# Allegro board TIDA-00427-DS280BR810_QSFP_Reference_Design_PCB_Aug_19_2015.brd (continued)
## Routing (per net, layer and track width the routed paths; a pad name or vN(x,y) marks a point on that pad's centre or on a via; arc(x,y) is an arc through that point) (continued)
RXN0_CABLE_TOP: length 68.6
  TOP w0.16: U1.A9 v2(94.73,68.6)
  ART09 w0.109: v2(94.73,68.6) 94.4,68.27 arc(94.37,68.22) 94.36,68.17 94.36,68.04 arc(94.4,67.95) 94.49,67.91 95.5,67.91 arc(95.85,67.98) 96.14,68.17 96.24,68.28 arc(96.97,68.76) 97.83,68.94 98.07,68.94 arc(99.84,69.67) 100.58,71.45 100.58,75.06 arc(100.9,76.68) 101.82,78.06 102.42,78.66 arc(105.33,80.6) 108.75,81.28 119.49,81.28 arc(120.26,81.13) 120.9,80.7 arc(121.66,80.19) 122.56,80.01 146.81,80.01 arc(148.34,79.38) 148.97,77.85 148.97,77.55 arc(149.03,77.26) 149.22,77.04 arc(149.4,76.89) 149.53,76.71 149.69,76.42 149.76,76.31 arc(149.84,76.24) 149.94,76.26 U9.U18
RXN0_HOST_BOT: length 73.7
  TOP w0.16: U2.B1 v2(113.59,63.27)
  ART11 w0.109: U8.L18 50.03,63.64 50.21,63.59 50.27,63.47 50.4,63.25 50.57,62.95 50.75,62.65 arc(51.1,61.79) 51.23,60.88 arc(51.31,60.45) 51.56,60.09 53.54,58.11 arc(54.61,57.4) 55.87,57.14 76.89,57.14 arc(78.11,56.9) 79.15,56.21 79.54,55.82 arc(80.79,54.98) 82.27,54.69 96.4,54.69 arc(101.86,55.77) 106.49,58.86 109.47,61.85 110.56,62.93 arc(111.75,63.73) 113.16,64.01 113.78,64.01 arc(113.9,63.96) 113.96,63.83 113.96,63.7 arc(113.95,63.65) 113.92,63.6 v2(113.59,63.27)
RXN0_HOST_TOP: length 69.6
  TOP w0.16: U2.A9 v2(112.53,71)
  ART09 w0.109: U8.U18 58.02,63.63 58.2,63.58 58.42,63.19 arc(58.46,63.13) 58.49,63.07 58.5,63.07 58.59,62.97 arc(58.77,62.68) 58.82,62.34 58.81,62.04 58.81,62.03 arc(59.68,59.92) 61.79,59.05 73.23,59.05 arc(74.4,58.82) 75.38,58.16 arc(77.01,57.07) 78.94,56.69 98.97,56.69 arc(102.47,57.39) 105.44,59.37 arc(105.46,59.38) 105.47,59.39 arc(105.48,59.4) 105.49,59.4 arc(105.49,59.41) 105.5,59.41 arc(105.5,59.41) 105.5,59.41 arc(105.5,59.41) 105.5,59.42 105.77,59.68 arc(107.29,61.96) 107.82,64.64 107.82,67.31 arc(107.96,68.01) 108.36,68.61 110.15,70.4 111.21,71.46 arc(111.46,71.63) 111.76,71.69 112.77,71.69 arc(112.86,71.65) 112.9,71.56 112.9,71.42 arc(112.89,71.37) 112.86,71.33 v2(112.53,71)
RXN1_CABLE_BOT: length 71.4
  TOP w0.132: 94.49,72.18 94.47,72.2 U1.A5
  TOP w0.16: 94.49,72.18 94.58,72.18 arc(94.71,72.16) 94.82,72.08 95,71.91 arc(95.17,71.77) 95.38,71.67 arc(95.52,71.64) 95.67,71.63 95.93,71.63 arc(96.24,71.68) 96.51,71.83 97.13,72.44 arc(97.29,72.55) v2(97.48,72.59)
  ART11 w0.109: U9.L21 153.94,76.26 arc(153.84,76.24) 153.76,76.31 153.69,76.42 153.53,76.71 arc(153.4,76.89) 153.22,77.04 arc(153.03,77.26) 152.97,77.55 152.97,77.77 arc(152.73,78.96) 152.06,79.97 150.24,81.79 arc(148.97,82.63) 147.48,82.93 129.51,82.93 arc(128.01,83.23) 126.75,84.07 arc(125.19,85.11) 123.36,85.48 118.87,85.48 arc(113.73,84.45) 109.37,81.54 100.46,72.63 arc(100.05,72.28) 99.58,72 arc(98.83,71.73) 98.04,71.63 97.51,71.63 arc(97.23,71.75) 97.11,72.03 97.11,72.16 arc(97.12,72.21) 97.15,72.25 v2(97.48,72.59)
RXN1_CABLE_TOP: length 62.5
  TOP w0.16: U1.A13 v2(94.73,65.4)
  ART11 w0.109: U9.U21 145.94,76.26 arc(145.84,76.24) 145.76,76.31 145.69,76.42 145.51,76.73 arc(145.23,77.07) 144.86,77.3 arc(144.54,77.39) 144.21,77.4 132.57,77.4 arc(127.49,78.41) 123.19,81.28 arc(122.2,81.94) 121.03,82.17 118.03,82.17 arc(114.71,81.51) 111.89,79.63 107.31,75.06 101.09,68.83 97.46,65.2 arc(96.56,64.6) 95.5,64.39 94.81,64.39 arc(94.49,64.52) 94.36,64.84 94.36,64.97 arc(94.37,65.02) 94.4,65.07 v2(94.73,65.4)
RXN1_HOST_BOT: length 67.5
  TOP w0.132: 112.84,67.4 U2.A5
  TOP w0.16: 112.84,67.4 112.8,67.4 112.78,67.42 112.69,67.42 arc(112.55,67.44) 112.44,67.52 112.27,67.69 arc(112.09,67.83) 111.88,67.92 arc(111.74,67.96) 111.59,67.97 111.34,67.97 arc(111.03,67.92) 110.75,67.77 110.14,67.16 arc(109.98,67.05) v2(109.78,67.01)
  ART11 w0.109: v2(109.78,67.01) 110.11,67.34 arc(110.14,67.39) 110.15,67.44 110.15,67.57 arc(110.04,67.83) 109.78,67.94 109.57,67.94 arc(108.39,67.76) 107.31,67.23 arc(107.05,67.03) 106.81,66.8 100.14,60.13 arc(97.68,58.49) 94.78,57.91 84.33,57.91 arc(83.37,58.1) 82.55,58.65 82.22,58.98 arc(81.02,59.78) 79.6,60.07 58.29,60.07 arc(56.5,60.55) 55.19,61.87 54.64,62.83 54.27,63.47 54.21,63.59 54.03,63.64 U8.L21
RXN1_HOST_TOP: length 65.1
  TOP w0.16: U2.A13 v2(112.53,74.2)
  ART09 w0.109: U8.U21 62.02,63.63 62.2,63.58 62.42,63.19 arc(62.44,63.16) 62.45,63.13 62.46,63.13 62.52,63.01 arc(62.76,62.73) 63.1,62.59 63.1,62.58 arc(63.65,62.51) 64.22,62.48 74.37,62.48 arc(75.87,62.18) 77.13,61.34 arc(78.9,60.16) 80.98,59.74 98.1,59.74 arc(100.77,60.27) 103.03,61.78 arc(103.05,61.79) 103.06,61.8 arc(103.07,61.81) 103.08,61.82 arc(103.08,61.82) 103.08,61.82 arc(103.09,61.82) 103.09,61.83 arc(103.09,61.83) 103.09,61.83 103.24,61.98 arc(104.56,63.96) 105.03,66.29 105.03,70.96 arc(105.34,72.53) 106.23,73.86 arc(106.79,74.34) 107.43,74.72 arc(108.4,75.07) 109.43,75.18 112.48,75.18 arc(112.78,75.06) 112.9,74.76 112.9,74.62 arc(112.89,74.57) 112.86,74.53 v2(112.53,74.2)
RXN2_CABLE_BOT: length 74.9
  TOP w0.16: U1.A3 v2(94.73,74.2)
  ART09 w0.109: U9.L15 157.94,73.86 arc(157.84,73.84) 157.76,73.91 157.69,74.02 157.43,74.48 arc(157.03,74.87) 156.48,74.99 arc(156.01,75.19) 155.82,75.66 155.82,76.55 arc(155.61,77.56) 155.04,78.42 153.26,80.2 arc(151.78,81.19) 150.03,81.53 124.31,81.53 arc(122.95,81.8) 121.79,82.58 arc(121.34,82.88) 120.81,82.98 108.92,82.98 arc(104.68,82.14) 101.09,79.74 100.53,79.18 arc(99.93,78.47) 99.46,77.67 arc(99.06,76.52) 98.93,75.31 arc(98.52,74.33) 97.54,73.92 96.16,73.92 arc(95.96,73.88) 95.78,73.76 arc(95.5,73.58) 95.18,73.51 94.49,73.51 arc(94.4,73.55) 94.36,73.64 94.36,73.77 arc(94.37,73.82) 94.4,73.87 v2(94.73,74.2)
RXN2_CABLE_TOP: length 70.8
  TOP w0.132: U1.A11 94.38,67.4 94.39,67.41
  TOP w0.16: 94.39,67.41 94.4,67.42 94.61,67.42 arc(94.69,67.43) 94.75,67.47 94.87,67.59 95,67.72 arc(95.18,67.86) 95.38,67.94 arc(95.49,67.96) 95.6,67.97 95.93,67.97 arc(96.26,67.91) 96.54,67.75 97.14,67.15 arc(97.29,67.05) v2(97.48,67.01)
  ART09 w0.109: U9.U15 149.94,73.86 arc(149.84,73.84) 149.76,73.91 149.69,74.02 149.43,74.48 arc(149.03,74.87) 148.48,74.99 arc(148.01,75.19) 147.82,75.66 147.82,76.66 arc(147.71,77.19) 147.41,77.64 arc(146.75,78.08) 145.97,78.23 121.48,78.23 arc(120.62,78.4) 119.89,78.89 arc(119.13,79.4) 118.23,79.58 108.5,79.58 arc(106.08,79.1) 104.03,77.73 103.22,76.92 arc(102.3,75.54) 101.98,73.91 101.98,70.34 arc(101.58,68.36) 100.46,66.67 arc(100.1,66.37) 99.69,66.12 arc(99.02,65.87) 98.31,65.79 97.78,65.79 arc(97.31,65.98) 97.11,66.45 97.11,66.59 arc(97.12,66.64) 97.15,66.68 v2(97.48,67.01)
RXN2_HOST_BOT: length 73.1
  TOP w0.16: U2.A3 v2(112.53,65.4)
  ART11 w0.109: U8.L15 50.03,66.04 50.21,65.99 50.27,65.87 50.57,65.35 arc(50.91,65.02) 51.37,64.92 arc(51.86,64.72) 52.05,64.24 52.05,63.76 arc(52.3,62.54) 52.99,61.5 54.17,60.32 arc(56,59.1) 58.16,58.67 77.78,58.67 arc(79.63,58.3) 81.2,57.25 81.51,56.95 arc(82.27,56.44) 83.16,56.26 96.52,56.26 arc(100.98,57.15) 104.76,59.67 110.49,65.41 arc(111.33,65.97) 112.33,66.17 112.69,66.17 arc(112.84,66.11) 112.9,65.96 112.9,65.82 arc(112.89,65.77) 112.86,65.73 v2(112.53,65.4)
RXN2_HOST_TOP: length 71.6
  TOP w0.16: U2.A11 112.89,72.2 112.87,72.18 112.65,72.18 arc(112.57,72.17) 112.51,72.12 112.39,72.01 112.26,71.87 arc(112.09,71.74) 111.89,71.66 arc(111.78,71.64) 111.67,71.63 111.34,71.63 arc(111.01,71.69) 110.72,71.85 110.13,72.44 arc(109.97,72.55) v2(109.78,72.59)
  ART09 w0.109: U8.U15 57.96,66 arc(58.08,66.05) 58.2,65.98 58.41,65.67 58.67,65.29 arc(58.97,65.03) 59.36,64.94 arc(59.88,64.73) 60.09,64.21 60.09,63.44 arc(60.23,62.74) 60.62,62.15 60.97,61.8 arc(62.33,60.89) 63.93,60.57 74.17,60.57 arc(75.27,60.36) 76.19,59.74 arc(77.83,58.65) 79.75,58.26 98.56,58.26 arc(101.68,58.88) 104.32,60.65 104.55,60.88 arc(105.94,62.95) 106.43,65.41 106.43,69.4 arc(106.65,70.85) 107.31,72.17 arc(107.56,72.48) 107.82,72.77 107.92,72.87 arc(108.52,73.27) 109.22,73.41 109.89,73.41 arc(110.08,73.33) 110.15,73.14 110.15,73.01 arc(110.14,72.96) 110.11,72.92 v2(109.78,72.59)
RXN3_CABLE_BOT: length 72
  TOP w0.16: U1.A7 v2(94.73,71)
  ART11 w0.109: v2(94.73,71) 94.4,70.67 arc(94.37,70.62) 94.36,70.57 94.36,70.44 arc(94.46,70.2) 94.7,70.1 98.42,70.1 arc(99.07,70.16) 99.69,70.31 arc(100.54,70.7) 101.27,71.28 110.81,80.83 arc(114.42,83.23) 118.66,84.08 122.09,84.08 arc(123.92,83.71) 125.48,82.68 arc(126.74,81.83) 128.24,81.53 147.15,81.53 arc(148.48,81.27) 149.61,80.52 150.49,79.63 arc(151.49,78.13) 151.85,76.37 151.85,75.93 arc(152.05,75.3) 152.63,74.98 arc(153.12,74.79) 153.48,74.4 153.69,74.02 153.76,73.91 arc(153.84,73.84) 153.94,73.86 U9.L24
RXN3_CABLE_TOP: length 65.1
  TOP w0.16: v2(93.68,63.27) 93.64,63.27 arc(93.52,63.31) 93.44,63.41 93.35,63.63 arc(93.34,63.67) 93.33,63.72 U1.B15
  ART11 w0.109: v2(93.68,63.27) 93.35,62.94 arc(93.32,62.9) 93.31,62.85 93.31,62.71 arc(93.41,62.46) 93.67,62.36 94.11,62.36 arc(96.69,62.87) 98.88,64.33 107.31,72.77 112.47,77.93 arc(112.56,78.02) 112.65,78.11 arc(115.18,79.7) 118.11,80.26 119.67,80.26 arc(121.16,79.97) 122.43,79.12 arc(122.97,78.6) 123.52,78.11 arc(124.29,77.47) 125.09,76.88 arc(130.67,74.11) 136.83,73.16 141.48,73.16 arc(142.13,73.29) 142.69,73.66 143.75,74.72 arc(144.09,74.95) 144.49,75.03 arc(144.87,74.95) 145.18,74.74 145.38,74.55 arc(145.41,74.51) 145.43,74.48 145.52,74.32 145.69,74.02 145.76,73.91 arc(145.84,73.84) 145.94,73.86 U9.U24
RXN3_HOST_BOT: length 68.1
  TOP w0.16: U2.A7 v2(112.53,68.6)
  ART11 w0.109: U8.L24 54.02,66.03 54.2,65.98 54.27,65.87 54.46,65.53 arc(54.75,65.17) 55.14,64.93 arc(55.36,64.88) 55.58,64.89 arc(55.92,64.73) 56.05,64.39 56.05,63.68 arc(56.24,62.76) 56.76,61.97 56.77,61.97 arc(57.23,61.69) 57.77,61.59 81.61,61.59 arc(82.81,61.35) 83.83,60.67 84.3,60.2 arc(84.89,59.8) 85.59,59.66 95.5,59.66 arc(96.65,59.89) 97.63,60.54 103.76,66.67 arc(105.41,68.01) 107.31,68.96 arc(109.03,69.44) 110.81,69.6 112.46,69.6 arc(112.77,69.47) 112.9,69.16 112.9,69.02 arc(112.89,68.97) 112.86,68.93 v2(112.53,68.6)
RXN3_HOST_TOP: length 67.3
  TOP w0.16: v2(113.59,76.33) 113.62,76.33 arc(113.74,76.29) 113.82,76.19 113.91,75.97 arc(113.93,75.92) 113.93,75.88 U2.B15
  ART09 w0.109: U8.U24 62.02,66.03 62.2,65.98 62.42,65.59 arc(62.83,65.13) 63.38,64.86 arc(63.7,64.72) 63.93,64.46 arc(64.44,63.94) 65.15,63.75 75.85,63.75 arc(77.25,63.47) 78.43,62.68 arc(80.06,61.6) 81.97,61.21 97.92,61.21 arc(99.91,61.61) 101.6,62.74 102.12,63.26 arc(103.24,64.93) 103.63,66.91 103.63,71.22 arc(104.13,73.71) 105.54,75.82 arc(106.37,76.49) 107.31,76.98 arc(108.25,77.25) 109.22,77.34 113.5,77.34 arc(113.82,77.21) 113.96,76.88 113.96,76.75 arc(113.95,76.7) 113.92,76.66 v2(113.59,76.33)
RXP0_CABLE_BOT: length 74.9
  TOP w0.16: U1.C1 v2(92.68,76.33)
  ART09 w0.109: U9.L17 157.48,76 arc(157.55,76.08) 157.53,76.18 157.47,76.29 157.29,76.6 arc(157.25,76.66) 157.2,76.7 arc(157.15,76.74) 157.1,76.79 arc(156.89,77.13) 156.81,77.52 156.81,77.72 arc(156.6,78.81) 155.98,79.73 154.69,81.03 arc(152.72,82.34) 150.41,82.8 125.14,82.8 arc(123.94,83.04) 122.93,83.71 arc(122.26,84.16) 121.46,84.32 108.84,84.32 arc(103.79,83.32) 99.5,80.45 98.77,79.72 arc(98.26,78.97) 98.05,78.09 arc(98.05,78.04) 98.05,77.98 arc(97.94,77.41) 97.61,76.93 96.7,76.02 arc(95.92,75.49) 94.99,75.31 93.51,75.31 arc(93.18,75.44) 93.05,75.77 93.05,75.9 arc(93.04,75.95) 93.01,75.99 v2(92.68,76.33)
RXP0_CABLE_TOP: length 68.6
  TOP w0.16: v2(93.73,68.6) 93.73,68.64 arc(93.72,68.68) 93.7,68.71 93.47,68.94 arc(93.41,68.98) U1.B9
  ART09 w0.109: v2(93.73,68.6) 94.06,68.27 arc(94.09,68.22) 94.1,68.17 94.1,68.04 arc(94.22,67.77) 94.49,67.65 95.5,67.65 arc(95.93,67.74) 96.3,67.98 arc(96.31,67.99) 96.33,68 arc(96.34,68.01) 96.34,68.01 arc(96.35,68.02) 96.35,68.02 arc(96.35,68.02) 96.36,68.02 arc(96.36,68.03) 96.36,68.03 96.42,68.09 arc(97.07,68.52) 97.83,68.68 98.07,68.68 arc(100.03,69.49) 100.84,71.45 100.84,75.06 arc(101.14,76.58) 102.01,77.88 102.6,78.47 arc(105.42,80.36) 108.75,81.02 119.49,81.02 arc(120.16,80.89) 120.72,80.51 arc(121.56,79.95) 122.56,79.75 146.81,79.75 arc(148.16,79.19) 148.71,77.85 148.71,77.55 arc(148.8,77.14) 149.08,76.82 arc(149.2,76.71) 149.3,76.58 149.47,76.29 149.53,76.18 arc(149.55,76.08) 149.48,76 U9.U17
RXP0_HOST_BOT: length 73.6
  TOP w0.16: U2.C1 v2(114.59,63.27)
  ART11 w0.109: v2(114.59,63.27) 114.25,63.6 arc(114.22,63.65) 114.21,63.7 114.21,63.83 arc(114.09,64.14) 113.78,64.27 113.16,64.27 arc(111.65,63.97) 110.37,63.11 106.31,59.05 arc(101.76,56.01) 96.4,54.95 82.27,54.95 arc(80.89,55.22) 79.72,56 79.37,56.36 arc(79.36,56.36) 79.36,56.36 arc(79.36,56.36) 79.36,56.36 arc(79.36,56.37) 79.35,56.37 arc(79.34,56.38) 79.34,56.38 arc(79.32,56.39) 79.31,56.4 arc(78.2,57.14) 76.89,57.4 55.87,57.4 arc(54.71,57.64) 53.72,58.29 51.74,60.27 arc(51.55,60.55) 51.49,60.88 arc(51.35,61.86) 50.97,62.77 50.8,63.08 50.43,63.71 50.48,63.89 U8.L17
RXP0_HOST_TOP: length 69.5
  TOP w0.16: v2(113.53,71) 113.53,70.96 arc(113.54,70.92) 113.56,70.89 113.79,70.66 arc(113.86,70.61) U2.B9
  ART09 w0.109: U8.U17 58.89,64.13 58.47,63.89 58.42,63.71 58.45,63.67 58.54,63.5 58.65,63.32 arc(58.67,63.28) 58.69,63.25 58.69,63.25 58.78,63.15 arc(59.01,62.77) 59.08,62.33 59.07,62.03 arc(59.86,60.11) 61.79,59.31 73.23,59.31 arc(74.5,59.06) 75.56,58.34 arc(77.11,57.31) 78.94,56.95 98.97,56.95 arc(102.39,57.63) 105.28,59.56 105.58,59.86 arc(107.05,62.06) 107.56,64.64 107.56,67.31 arc(107.72,68.11) 108.18,68.79 110,70.61 111.03,71.65 arc(111.36,71.87) 111.76,71.95 112.77,71.95 arc(113.05,71.83) 113.16,71.56 113.16,71.42 arc(113.17,71.37) 113.2,71.33 v2(113.53,71)
RXP1_CABLE_BOT: length 71.5
  TOP w0.132: 94.47,72.58 94.46,72.57 94.13,72.57 arc(93.99,72.54) 93.87,72.46 93.7,72.3 arc(93.6,72.22) 93.47,72.2 U1.B5
  TOP w0.16: 94.47,72.58 94.48,72.59 94.58,72.59 arc(94.87,72.53) 95.11,72.37 95.28,72.2 arc(95.39,72.11) 95.5,72.06 arc(95.59,72.04) 95.67,72.03 95.93,72.03 arc(96.32,72.2) v2(96.48,72.59)
  ART11 w0.109: v2(96.48,72.59) 96.81,72.25 arc(96.84,72.21) 96.85,72.16 96.85,72.03 arc(97.04,71.57) 97.51,71.37 98.04,71.37 arc(98.89,71.47) 99.69,71.77 arc(100.2,72.07) 100.65,72.45 109.55,81.36 arc(113.83,84.21) 118.87,85.22 123.36,85.22 arc(125.09,84.87) 126.56,83.89 arc(127.91,82.99) 129.51,82.67 147.48,82.67 arc(148.88,82.39) 150.06,81.6 151.84,79.82 arc(151.84,79.82) 151.84,79.82 arc(151.84,79.82) 151.85,79.82 151.88,79.79 arc(152.49,78.86) 152.71,77.77 152.71,77.55 arc(152.8,77.14) 153.08,76.82 arc(153.2,76.71) 153.3,76.58 153.47,76.29 153.53,76.18 arc(153.55,76.08) 153.48,76 U9.L22
RXP1_CABLE_TOP: length 62.5
  TOP w0.16: U1.B13 93.33,65.8 v2(93.73,65.4)
  ART11 w0.109: U9.U22 145.48,76 arc(145.55,76.08) 145.53,76.18 145.47,76.29 145.29,76.61 arc(145.06,76.88) 144.76,77.06 arc(144.51,77.13) 144.25,77.14 arc(144.24,77.14) 144.23,77.14 arc(144.23,77.14) 144.22,77.14 arc(144.22,77.14) 144.22,77.14 132.57,77.14 arc(127.39,78.17) 123.01,81.1 arc(122.1,81.7) 121.03,81.92 118.03,81.92 arc(114.81,81.27) 112.07,79.45 107.5,74.87 101.28,68.65 97.64,65.01 arc(96.66,64.36) 95.5,64.13 94.81,64.13 arc(94.31,64.34) 94.1,64.84 94.1,64.97 arc(94.09,65.02) 94.06,65.07 v2(93.73,65.4)
RXP1_HOST_BOT: length 67.6
  TOP w0.132: 112.84,67.03 113.13,67.03 arc(113.27,67.06) 113.39,67.14 113.56,67.3 arc(113.67,67.37) 113.79,67.4 U2.B5
  TOP w0.16: 112.84,67.03 112.8,67.03 112.78,67.01 112.68,67.01 arc(112.4,67.07) 112.15,67.23 111.98,67.4 arc(111.88,67.48) 111.76,67.54 arc(111.68,67.56) 111.59,67.56 111.34,67.56 arc(110.94,67.4) v2(110.78,67.01)
  ART11 w0.109: 54.86,62.96 55.01,62.7 55.41,62 arc(56.63,60.77) 58.29,60.33 79.6,60.33 arc(81.1,60.02) 82.38,59.17 arc(82.4,59.16) 82.41,59.15 arc(82.42,59.15) 82.43,59.14 arc(82.43,59.14) 82.43,59.13 arc(82.44,59.13) 82.44,59.13 arc(82.44,59.13) 82.44,59.13 82.73,58.83 arc(83.47,58.34) 84.33,58.17 94.78,58.17 arc(97.58,58.73) 99.95,60.31 106.62,66.99 arc(106.88,67.23) 107.17,67.44 arc(108.31,68.01) 109.57,68.2 109.78,68.2 arc(110.23,68.02) 110.41,67.57 110.41,67.44 arc(110.42,67.39) 110.45,67.34 v2(110.78,67.01)
  ART11 w0.132: U8.L22 54.48,63.89 54.43,63.71 54.5,63.6 54.86,62.96 54.73,63.19
RXP1_HOST_TOP: length 64.9
  TOP w0.16: U2.B13 v2(113.53,74.2)
  ART09 w0.109: v2(113.53,74.2) 113.2,74.53 arc(113.17,74.57) 113.16,74.62 113.16,74.76 arc(112.96,75.24) 112.48,75.44 109.43,75.44 arc(108.34,75.32) 107.31,74.95 arc(106.64,74.55) 106.05,74.04 arc(105.1,72.63) 104.77,70.96 104.77,66.29 arc(104.33,64.06) 103.06,62.17 102.87,61.98 arc(100.68,60.51) 98.1,60 80.98,60 arc(79,60.39) 77.32,61.52 arc(75.97,62.42) 74.37,62.74 64.22,62.74 arc(63.68,62.76) 63.14,62.84 arc(62.91,62.94) 62.75,63.14 62.68,63.25 62.68,63.25 arc(62.66,63.28) 62.65,63.32 62.54,63.5 62.43,63.69 62.42,63.71 62.47,63.89 62.89,64.13 U8.U22
RXP2_CABLE_BOT: length 74.9
  TOP w0.16: U1.B3 v2(93.73,74.2)
  ART09 w0.109: U9.L14 157.48,73.6 arc(157.55,73.68) 157.53,73.78 157.47,73.89 157.2,74.36 arc(156.9,74.65) 156.5,74.73 156.48,74.73 arc(155.83,75.01) 155.56,75.66 155.56,76.55 arc(155.37,77.46) 154.86,78.23 153.08,80.01 arc(151.68,80.95) 150.03,81.27 124.31,81.27 arc(122.85,81.57) 121.61,82.39 arc(121.24,82.64) 120.81,82.72 108.92,82.72 arc(104.78,81.9) 101.27,79.55 100.71,79 arc(100.14,78.32) 99.69,77.56 arc(99.32,76.46) 99.19,75.31 arc(98.7,74.14) 97.54,73.66 96.16,73.66 arc(96.06,73.64) 95.97,73.58 arc(95.6,73.34) 95.18,73.25 94.49,73.25 arc(94.22,73.37) 94.1,73.64 94.1,73.77 arc(94.09,73.82) 94.06,73.87 v2(93.73,74.2)
RXP2_CABLE_TOP: length 70.8
  TOP w0.132: 94.38,67.03 94.13,67.03 arc(93.99,67.06) 93.87,67.14 93.7,67.3 arc(93.6,67.37) 93.47,67.4 U1.B11
  TOP w0.16: 94.38,67.03 94.38,67.03 94.4,67.01 94.62,67.01 arc(94.85,67.06) 95.04,67.19 95.29,67.44 arc(95.38,67.51) 95.48,67.55 arc(95.54,67.56) 95.6,67.56 95.93,67.56 arc(96.32,67.4) v2(96.48,67.01)
  ART09 w0.109: v2(96.48,67.01) 96.81,66.68 arc(96.84,66.64) 96.85,66.59 96.85,66.45 arc(97.12,65.8) 97.78,65.53 98.31,65.53 arc(99.08,65.62) 99.81,65.89 arc(100.25,66.16) 100.64,66.49 arc(101.82,68.26) 102.23,70.34 102.23,73.91 arc(102.54,75.44) 103.4,76.73 104.22,77.55 arc(106.18,78.86) 108.5,79.32 118.23,79.32 arc(119.03,79.16) 119.7,78.71 arc(120.52,78.16) 121.48,77.97 145.97,77.97 arc(146.65,77.84) 147.23,77.45 arc(147.47,77.09) 147.56,76.66 147.56,75.66 arc(147.83,75.01) 148.48,74.73 148.5,74.73 arc(148.9,74.65) 149.2,74.36 149.47,73.89 149.53,73.78 arc(149.55,73.68) 149.48,73.6 U9.U14
RXP2_HOST_BOT: length 72.9
  TOP w0.16: U2.B3 v2(113.53,65.4)
  ART11 w0.109: v2(113.53,65.4) 113.2,65.73 arc(113.17,65.77) 113.16,65.82 113.16,65.96 arc(113.02,66.29) 112.69,66.43 112.33,66.43 arc(111.25,66.21) 110.33,65.6 arc(110.31,65.59) 110.3,65.58 arc(110.29,65.57) 110.28,65.57 arc(110.28,65.56) 110.28,65.56 arc(110.27,65.56) 110.27,65.55 arc(110.27,65.55) 110.27,65.55 104.58,59.86 arc(100.88,57.39) 96.52,56.52 83.16,56.52 arc(82.37,56.68) 81.69,57.13 81.42,57.4 arc(81.42,57.4) 81.42,57.4 arc(81.42,57.4) 81.42,57.4 arc(81.41,57.41) 81.41,57.41 arc(81.4,57.42) 81.39,57.42 arc(81.38,57.44) 81.36,57.45 arc(79.72,58.54) 77.78,58.93 58.16,58.93 arc(56.1,59.34) 54.36,60.5 53.17,61.69 arc(52.54,62.64) 52.31,63.76 52.31,64.24 arc(52.04,64.9) 51.37,65.18 51.36,65.18 arc(51.03,65.25) 50.79,65.48 50.5,66 50.43,66.11 50.48,66.3 U8.L14
RXP2_HOST_TOP: length 71.5
  TOP w0.132: 112.95,72.57 113.13,72.57 arc(113.27,72.54) 113.39,72.46 113.56,72.3 arc(113.67,72.22) 113.79,72.2 U2.B11
  TOP w0.16: 112.95,72.57 112.89,72.57 112.87,72.59 112.65,72.59 arc(112.42,72.54) 112.22,72.41 111.97,72.16 arc(111.88,72.09) 111.78,72.05 arc(111.72,72.04) 111.67,72.03 111.34,72.03 arc(110.94,72.2) v2(110.78,72.59)
  ART09 w0.109: U8.U14 58.41,66.26 arc(58.4,66.19) 58.42,66.12 58.63,65.81 58.88,65.44 arc(59.09,65.26) 59.36,65.2 arc(60.06,64.91) 60.35,64.21 60.35,63.44 arc(60.47,62.84) 60.81,62.33 61.16,61.98 arc(62.43,61.13) 63.93,60.83 74.17,60.83 arc(75.36,60.6) 76.38,59.92 arc(77.93,58.88) 79.75,58.52 98.56,58.52 arc(101.58,59.12) 104.14,60.83 104.37,61.06 arc(105.7,63.05) 106.17,65.41 106.17,69.4 arc(106.41,70.93) 107.1,72.32 arc(107.36,72.65) 107.64,72.95 107.74,73.05 arc(108.42,73.51) 109.22,73.67 109.89,73.67 arc(110.26,73.51) 110.41,73.14 110.41,73.01 arc(110.42,72.96) 110.45,72.92 v2(110.78,72.59)
RXP3_CABLE_BOT: length 72
  TOP w0.16: U1.B7 v2(93.73,71)
  ART11 w0.109: v2(93.73,71) 94.06,70.67 arc(94.09,70.62) 94.1,70.57 94.1,70.44 arc(94.28,70.02) 94.7,69.84 98.42,69.84 arc(99.11,69.9) 99.78,70.06 arc(100.67,70.48) 101.45,71.1 111,80.64 arc(114.51,82.99) 118.66,83.82 122.09,83.82 arc(123.82,83.48) 125.29,82.49 arc(126.64,81.59) 128.24,81.27 147.15,81.27 arc(148.38,81.03) 149.42,80.33 150.31,79.45 arc(151.26,78.03) 151.59,76.37 151.59,75.93 arc(151.85,75.13) 152.59,74.72 arc(152.97,74.57) 153.25,74.27 153.47,73.89 153.53,73.78 arc(153.55,73.68) 153.48,73.6 U9.L25
RXP3_CABLE_TOP: length 65
  TOP w0.16: U1.C15 v2(92.68,63.27)
  ART11 w0.109: U9.U25 145.48,73.6 arc(145.55,73.68) 145.53,73.78 145.47,73.89 145.26,74.25 145.23,74.31 145.21,74.34 arc(145.2,74.35) 145.19,74.36 145,74.56 arc(144.77,74.71) 144.49,74.77 arc(144.19,74.71) 143.93,74.54 142.87,73.48 arc(142.23,73.05) 141.48,72.9 136.83,72.9 arc(130.59,73.86) 124.95,76.66 arc(124.13,77.27) 123.35,77.91 arc(122.79,78.41) 122.24,78.94 arc(121.06,79.73) 119.67,80 118.11,80 arc(115.27,79.46) 112.83,77.92 arc(112.74,77.83) 112.66,77.75 107.5,72.59 99.06,64.15 arc(96.79,62.63) 94.11,62.1 93.67,62.1 arc(93.23,62.28) 93.05,62.71 93.05,62.85 arc(93.04,62.9) 93.01,62.94 v2(92.68,63.27)
RXP3_HOST_BOT: length 68
  TOP w0.16: U2.B7 v2(113.53,68.6)
  ART11 w0.109: v2(113.53,68.6) 113.2,68.93 arc(113.17,68.97) 113.16,69.02 113.16,69.16 arc(112.96,69.65) 112.46,69.86 110.81,69.86 arc(108.99,69.69) 107.22,69.21 arc(105.27,68.23) 103.58,66.86 97.45,60.73 arc(96.55,60.13) 95.5,59.92 85.59,59.92 arc(84.99,60.04) 84.49,60.38 84.05,60.82 arc(84.05,60.82) 84.05,60.82 arc(84.05,60.82) 84.04,60.82 84.01,60.85 arc(82.91,61.59) 81.61,61.85 57.77,61.85 arc(57.33,61.93) 56.94,62.16 56.94,62.16 arc(56.48,62.86) 56.31,63.68 56.31,64.39 arc(56.09,64.93) 55.55,65.15 arc(55.39,65.13) 55.24,65.17 arc(54.92,65.37) 54.68,65.66 54.49,66 54.42,66.11 54.47,66.29 54.89,66.53 U8.L25
RXP3_HOST_TOP: length 67.1
  TOP w0.16: U2.C15 v2(114.59,76.33)
  ART09 w0.109: U8.U25 62.89,66.53 62.47,66.29 62.42,66.11 62.45,66.07 62.54,65.9 62.65,65.72 arc(62.98,65.33) 63.44,65.12 arc(63.85,64.92) 64.15,64.58 arc(64.57,64.16) 65.15,64.01 75.85,64.01 arc(77.35,63.71) 78.61,62.87 arc(80.15,61.83) 81.97,61.47 97.92,61.47 arc(99.81,61.85) 101.42,62.92 101.94,63.44 arc(103,65.03) 103.37,66.91 103.37,71.22 arc(103.89,73.81) 105.35,76 arc(106.22,76.71) 107.22,77.22 arc(108.2,77.51) 109.22,77.6 113.5,77.6 arc(114,77.39) 114.21,76.88 114.21,76.75 arc(114.22,76.7) 114.25,76.66 v2(114.59,76.33)
SCL: length 286.2
  TOP w0.183: U2.F12 v2(117.53,72.6) ; U1.F12 v2(89.73,67)
  ART02 w0.132: v2(117.53,72.6) 116.85,73.28 102.57,73.28 98.98,69.7 92.43,69.7 v2(89.73,67)
  ART04 w0.132: J18.6 15.49,35.94 15.49,44.58 16.76,45.85 18.49,45.85 J23.4 22.91,44.53 26.67,40.77 48.71,40.77 53.66,45.72 J3.1 81.89,67.92 88.81,67.92 v2(89.73,67) 89.86,67 90.42,67.56 90.42,68.2 89,69.62 84.68,69.62 82.3,72.01 82.3,85.47 81.41,86.36 81.41,88.98 J22.4 ; v2(117.53,72.6) 117.53,70.56 118.24,69.85 121.92,69.85 125.02,66.75 125.02,34.42 116.84,26.25 J4.3 116.84,25.53 118.11,24.26 126.24,24.26 144.27,42.29 173.74,42.29 175.9,44.45
SDA: length 271
  TOP w0.183: U1.E12 v2(91.33,67) ; U2.E12 v2(115.93,72.6)
  ART02 w0.132: v2(91.33,67) 92.01,66.32 102.18,66.32 105.82,69.95 114.48,69.95 115.93,71.41 v2(115.93,72.6)
  ART04 w0.132: v2(115.93,72.6) 116.38,73.05 119.61,73.05 125.48,67.18 125.48,34.16 119.38,28.07 J4.4 120.62,24.8 125.7,24.8 143.83,42.93 171.83,42.93 J24.3 ; J22.3 82.68,72.17 84.84,70 89.26,70 91.33,67.93 v2(91.33,67) 90.88,66.55 90.04,66.55 89.81,66.32 82.83,66.32 J3.2 61.15,44.64 53.28,44.64 48.9,40.26 26.29,40.26 23.24,43.31 19.18,43.31 17.96,44.53 J23.3 16.13,43.38 16.13,37.85 J18.5
TOP_INTL_CABLE: length 33.2
  TOP w0.183: J14.4 145.34,48.77 149.1,48.77 v1(150.5,50.16) 150.62,50.29 R45.1
  ART04 w0.132: v1(150.5,50.16) 149.86,50.8 149.86,60.33 147.58,62.62 147.58,69.46 146.12,70.93 U9.U28
TOP_INTL_HOST: length 61.3
  TOP w0.183: J13.4 28.63,48.26 31.11,48.26 v1(32.38,49.53) R41.1
  ART04 w0.132: v1(32.38,49.53) 33.78,48.13 33.78,44.16 35.69,42.26 47.91,42.26 54.56,48.9 54.56,53.35 60.37,59.16 60.37,66.84 60.95,67.42 61.53,67.42 62.89,68.78 U8.U28
TOP_LPMODE_CABLE: length 24.3
  ART04 w0.132: J14.8 149.22,47.57 149.22,57.39 143.89,62.73 143.89,67.41 U9.U31
TOP_LPMODE_HOST: length 58.3
  ART04 w0.132: U8.U31 64.22,69.99 64.22,62.4 54.99,53.17 54.99,48.6 48.11,41.72 33.4,41.72 31.24,43.88 31.24,45.8 J13.8
TOP_MODPRSL_CABLE: length 40.6
  TOP w0.183: R46.1 153.16,50.29 v1(153.03,50.16) 151.26,48.39 J14.10 150.16,45.97 142.19,45.97 J14.2
  ART04 w0.132: U9.U27 147.91,70.22 147.91,63.16 152.4,58.67 152.4,50.8 v1(153.03,50.16)
TOP_MODPRSL_HOST: length 64.3
  TOP w0.183: R42.1 v1(34.92,49.53) 35.05,49.4 J13.10 33.83,45.85 26.11,45.85 J13.2
  ART04 w0.132: U8.U27 61.02,68.13 60.03,67.13 60.03,59.5 54.08,53.55 54.08,49.1 47.71,42.73 37.59,42.73 36.45,43.88 36.45,48.01 v1(34.92,49.53)
TOP_MODSELL_CABLE: length 32.3
  ART04 w0.132: U9.U8 150.29,68.53 151.51,67.31 151.51,60.96 153.67,58.8 153.67,49.66 152.53,48.51 152.53,46.48 151.89,45.85 147.4,45.85 146.18,47.07
TOP_MODSELL_HOST: length 66.8
  ART04 w0.132: J13.6 28.83,45.92 28.83,43.75 31.37,41.21 48.32,41.21 55.5,48.39 55.5,52.96 64.6,62.06 64.6,70.4 63.12,71.88 62.69,71.88 62.13,71.33 U8.U8
TXN0_CABLE_BOT: length 44.9
  TOP w0.16: U2.H1 v2(119.08,63.27)
  ART09 w0.109: v2(119.08,63.27) 118.75,63.27 118.59,63.12 118.59,62.71 arc(118.78,62.27) 119.22,62.08 126.32,62.08 arc(128.12,61.72) 129.64,60.71 131.35,59 arc(132.88,57.97) 134.7,57.61 149.43,57.61 arc(152.86,59.03) 154.28,62.47 154.28,62.69 arc(154.25,62.9) 154.16,63.1 153.58,64.11 153.16,64.11 153.01,63.96 U9.L37
TXN0_CABLE_TOP: length 34.5
  TOP w0.16: U2.J9 v2(120.13,71)
  ART09 w0.109: v2(120.13,71) 119.76,71 119.61,70.85 119.61,70.51 arc(119.79,70.08) 120.21,69.91 124.46,69.91 arc(124.78,69.9) 125.09,69.88 arc(128.01,69.13) 130.48,67.41 134.8,63.09 arc(136.32,62.08) 138.11,61.72 145.48,61.72 arc(146.09,61.98) 146.35,62.59 146.35,62.74 arc(146.33,62.85) 146.28,62.95 145.58,64.03 145.16,64.03 145.01,63.88 U9.U37
TXN0_HOST_BOT: length 42.5
  TOP w0.16: U1.H1 v2(88.19,76.33)
  ART09 w0.109: v2(88.19,76.33) 88.54,76.33 88.7,76.48 88.7,76.71 arc(88.65,76.92) 88.54,77.1 88.33,77.3 87.15,78.49 arc(84.84,80.03) 82.12,80.57 57.07,80.57 arc(54.65,79.56) 53.64,77.14 53.64,76.99 arc(53.69,76.77) 53.81,76.58 54.06,76.21 54.15,76.07 54.36,75.77 54.66,75.77 54.89,75.99 U8.L37
TXN0_HOST_TOP: length 30.4
  TOP w0.16: U1.J9 v2(87.13,68.6)
  ART09 w0.109: U8.U37 62.74,76.13 62.46,75.84 62.46,75.6 62.71,75.23 62.95,74.98 arc(63.18,74.83) 63.45,74.78 63.7,74.78 arc(64.2,74.68) 64.61,74.4 64.8,74.22 arc(65.27,73.9) 65.83,73.79 77.75,73.79 arc(79.51,73.44) 80.99,72.45 84.86,68.58 arc(85.6,68.08) 86.48,67.91 87.29,67.91 arc(87.51,68) 87.6,68.22 87.6,68.45 87.45,68.6 v2(87.13,68.6)
TXN1_CABLE_BOT: length 49.3
  TOP w0.132: 119.87,67.4 U2.J5
  TOP w0.16: 119.87,67.4 119.88,67.42 119.98,67.42 arc(120.11,67.44) 120.22,67.52 120.4,67.69 arc(120.57,67.83) 120.78,67.92 arc(120.92,67.96) 121.07,67.97 121.41,67.97 arc(121.72,67.91) 121.99,67.75 122.62,67.12 arc(122.74,67.04) v2(122.88,67.01)
  ART11 w0.109: v2(122.88,67.01) 122.76,67.13 122.56,67.13 122.33,66.9 122.33,66.4 arc(122.38,66.15) 122.52,65.94 122.7,65.75 130.14,58.31 arc(132.22,56.93) 134.66,56.44 148.29,56.44 arc(150.96,56.97) 153.23,58.49 156.88,62.13 arc(157.18,62.34) 157.54,62.41 157.66,62.41 arc(157.87,62.45) 158.05,62.57 158.12,62.64 158.17,62.69 arc(158.21,62.76) 158.23,62.84 arc(158.2,63.04) 158.12,63.22 arc(158.06,63.31) 158.01,63.39 157.61,64.01 157.29,64.01 U9.L2
TXN1_CABLE_TOP: length 41.8
  TOP w0.16: U2.J13 v2(120.13,74.2)
  ART11 w0.109: U9.U2 149.01,63.85 149.12,63.96 149.68,63.96 150.14,63.14 arc(150.21,63.01) 150.24,62.87 arc(150.24,62.84) 150.24,62.81 150.24,62.64 arc(149.5,60.85) 147.72,60.11 138.48,60.11 arc(135.8,60.65) 133.53,62.17 133.43,62.26 126.76,68.93 126.1,69.59 124.75,70.95 arc(123.7,71.64) 122.47,71.89 120.8,71.89 arc(119.96,72.24) 119.61,73.08 119.61,74.05 119.76,74.2 v2(120.13,74.2)
TXN1_HOST_BOT: length 48.6
  TOP w0.132: 87.38,72.18 87.4,72.2 U1.J5
  TOP w0.16: 87.38,72.18 87.29,72.18 arc(87.15,72.16) 87.04,72.08 86.87,71.91 arc(86.69,71.77) 86.48,71.67 arc(86.34,71.64) 86.19,71.63 85.85,71.63 arc(85.54,71.68) 85.27,71.85 84.64,72.48 arc(84.52,72.56) v2(84.38,72.59)
  ART11 w0.109: v2(84.38,72.59) 84.79,72.59 84.94,72.74 84.94,73.18 arc(84.85,73.62) 84.6,74 84.25,74.35 78.27,80.33 arc(74.91,82.57) 70.94,83.36 60.59,83.36 arc(56.68,82.59) 53.37,80.37 50.83,77.83 arc(50.52,77.58) 50.14,77.5 arc(50.01,77.47) 49.91,77.39 49.77,77.25 arc(49.71,77.15) 49.68,77.04 49.68,76.91 arc(49.7,76.78) 49.76,76.67 50.3,75.82 50.75,75.82 50.89,75.96 U8.L2
TXN1_HOST_TOP: length 40.6
  TOP w0.16: U1.J13 v2(87.13,65.4)
  ART11 w0.109: v2(87.13,65.4) 87.18,65.35 87.53,65.35 87.68,65.51 87.68,66.03 arc(87.2,67.2) 86.03,67.69 85.65,67.69 arc(83.88,68.04) 82.39,69.04 75.7,75.72 arc(75.7,75.73) 75.7,75.73 arc(75.7,75.73) 75.69,75.73 75.66,75.76 arc(71.43,78.59) 66.45,79.58 60.02,79.58 arc(58.35,78.89) 57.66,77.22 57.66,77.04 arc(57.68,76.89) 57.73,76.76 58.22,75.92 58.68,75.92 U8.U2
TXN2_CABLE_BOT: length 45.2
  TOP w0.16: U2.J3 v2(120.13,65.4)
  ART09 w0.109: v2(120.13,65.4) 119.76,65.77 119.76,65.9 arc(119.8,66) 119.9,66.04 124.36,66.04 arc(124.72,66.03) 125.07,66.01 arc(127.89,65.26) 130.28,63.59 133.65,60.22 arc(134.88,59.39) 136.33,59.11 147.09,59.11 arc(150.45,60.5) 151.84,63.86 151.84,67.03 arc(151.94,67.33) 152.2,67.51 152.65,67.51 arc(152.88,67.46) 153.06,67.32 153.43,66.73 153.43,66.73 153.59,66.47 153.59,66.27 153.42,66.09 153.05,66.09 U9.L34
TXN2_CABLE_TOP: length 31.3
  TOP w0.132: U2.J11 119.73,72.2
  TOP w0.16: 119.73,72.2 119.78,72.2 119.8,72.18 119.82,72.18 arc(120.25,72.36) 120.42,72.78 arc(120.53,73.05) 120.8,73.16 121.93,73.16 arc(122.11,73.12) 122.27,73.02 arc(122.32,72.74) 122.08,72.59 v2(121.88,72.59)
  ART09 w0.109: U9.U34 145.17,65.96 145.39,65.96 145.54,66.11 145.54,66.62 145.08,67.32 144.99,67.42 arc(144.84,67.52) 144.65,67.56 138.37,67.56 arc(136.15,68) 134.28,69.25 133.78,69.75 arc(131.99,70.95) 129.87,71.37 123.27,71.37 arc(122.69,71.61) 122.45,72.19 122.45,72.45 122.31,72.59 v2(121.88,72.59)
TXN2_HOST_BOT: length 42.3
  TOP w0.16: U1.J3 v2(87.13,74.2)
  ART09 w0.109: U8.L34 54.75,73.73 54.51,73.48 54.51,73.15 54.57,73.06 54.87,72.68 54.97,72.58 arc(55.18,72.44) 55.42,72.39 55.6,72.39 arc(55.92,72.52) 56.05,72.85 56.05,76 arc(56.18,76.64) 56.54,77.18 arc(57.97,78.13) 59.65,78.47 77.94,78.47 arc(79.54,78.15) 80.9,77.24 83.13,75.01 83.36,74.78 arc(84.74,73.86) 86.36,73.54 87.41,73.54 arc(87.6,73.62) 87.68,73.81 87.68,74.05 87.53,74.2 v2(87.13,74.2)
TXN2_HOST_TOP: length 30.8
  TOP w0.132: 87.45,67.42 87.46,67.41 87.48,67.41 87.49,67.4 U1.J11
  TOP w0.16: 87.45,67.42 87.25,67.42 arc(87.17,67.43) 87.11,67.47 87,67.59 86.86,67.72 arc(86.69,67.86) 86.49,67.94 arc(86.38,67.96) 86.27,67.97 85.94,67.97 arc(85.61,67.91) 85.32,67.75 84.73,67.15 arc(84.57,67.05) v2(84.38,67.01)
  ART09 w0.109: U8.U34 62.61,73.73 62.46,73.58 62.46,73.3 62.8,72.69 arc(63.05,72.46) 63.37,72.39 64.12,72.39 arc(64.88,72.24) 65.53,71.81 arc(65.81,71.62) 66.13,71.56 73.63,71.56 arc(75.93,71.1) 77.88,69.8 80.67,67.01 arc(81.25,66.56) 81.92,66.29 arc(82.26,66.22) 82.62,66.2 84.56,66.2 arc(84.81,66.3) 84.91,66.55 84.91,66.9 84.76,67.06 84.43,67.06 v2(84.38,67.01)
TXN3_CABLE_BOT: length 51
  TOP w0.16: U2.J7 v2(120.13,68.6)
  ART11 w0.109: U9.L5 157.48,66.13 157.61,66.25 157.61,66.55 157.06,67.31 arc(156.87,67.48) 156.62,67.54 156.46,67.54 arc(156.05,67.38) 155.85,66.98 155.85,63.8 arc(155.72,63.14) 155.34,62.57 154.3,61.52 arc(150.41,58.93) 145.82,58.01 138.8,58.01 arc(135.08,58.75) 131.93,60.86 125.09,67.69 124.34,68.45 arc(122.98,69.35) 121.39,69.67 120.19,69.67 arc(119.89,69.55) 119.76,69.24 119.76,68.97 v2(120.13,68.6)
TXN3_CABLE_TOP: length 45.1
  TOP w0.16: U2.H15 v2(119.08,76.33)
  ART11 w0.109: v2(119.08,76.33) 118.82,76.33 118.67,76.48 118.67,76.89 arc(118.77,77.14) 119.02,77.24 119.53,77.24 arc(120.89,76.97) 122.05,76.2 134.21,64.03 arc(136.86,62.27) 139.98,61.65 145.88,61.65 arc(147.28,62.23) 147.86,63.63 147.86,67.11 arc(147.98,67.39) 148.26,67.51 148.72,67.51 arc(148.91,67.46) 149.06,67.33 149.56,66.55 149.56,66.24 149.44,66.13 U9.U5
TXN3_HOST_BOT: length 50.5
  TOP w0.16: U1.J7 v2(87.13,71)
  ART11 w0.109: U8.L5 50.61,73.73 50.44,73.56 50.44,73.27 50.97,72.52 arc(51.1,72.42) 51.26,72.39 51.57,72.39 arc(51.91,72.53) 52.05,72.87 52.05,76.24 arc(52.25,77.25) 52.83,78.11 53.14,78.42 arc(56.84,80.9) 61.21,81.77 69.19,81.77 arc(72.7,81.07) 75.68,79.08 83.1,71.67 83.97,70.8 arc(84.76,70.27) 85.7,70.08 87.1,70.08 arc(87.46,70.23) 87.6,70.59 87.6,70.85 87.45,71 v2(87.13,71)
TXN3_HOST_TOP: length 43.9
  TOP w0.16: U1.H15 v2(88.19,63.27)
  ART11 w0.109: U8.U5 58.59,73.73 58.37,73.51 58.37,73.33 59.02,72.46 arc(59.19,72.35) 59.39,72.31 59.63,72.31 arc(59.94,72.44) 60.07,72.75 60.07,75.95 arc(60.64,77.33) 62.03,77.91 64.11,77.91 arc(70.49,76.64) 75.89,73.03 78.56,70.36 86,62.92 arc(86.6,62.52) 87.3,62.38 88.29,62.38 arc(88.58,62.5) 88.7,62.79 88.7,63.12 88.54,63.27 v2(88.19,63.27)
TXP0_CABLE_BOT: length 45.1
  TOP w0.16: U2.G1 v2(118.08,63.27)
  ART09 w0.109: U9.L36 154,64.11 154,63.91 154.38,63.23 154.38,63.23 arc(154.5,62.97) 154.54,62.69 154.54,62.47 arc(153.04,58.85) 149.43,57.35 134.7,57.35 arc(132.79,57.73) 131.17,58.82 129.46,60.52 arc(128.02,61.49) 126.32,61.82 119.22,61.82 arc(118.59,62.08) 118.33,62.71 118.33,63.02 v2(118.08,63.27)
TXP0_CABLE_TOP: length 34.7
  TOP w0.16: U2.H9 v2(119.13,71)
  ART09 w0.109: U9.U36 145.96,64.08 145.96,63.92 146.49,63.1 146.49,63.09 arc(146.58,62.92) 146.61,62.74 146.61,62.59 arc(146.28,61.79) 145.48,61.46 138.11,61.46 arc(136.23,61.84) 134.64,62.9 arc(134.62,62.91) 134.61,62.92 arc(134.6,62.93) 134.59,62.93 arc(134.59,62.94) 134.58,62.94 arc(134.58,62.94) 134.58,62.94 arc(134.58,62.95) 134.58,62.95 130.3,67.23 arc(127.9,68.9) 125.08,69.62 arc(124.77,69.64) 124.46,69.65 120.21,69.65 arc(119.6,69.9) 119.35,70.51 119.35,70.78 v2(119.13,71)
TXP0_HOST_BOT: length 42.7
  TOP w0.16: U1.G1 v2(89.19,76.33)
  ART09 w0.109: v2(89.19,76.33) 88.96,76.56 88.96,76.71 arc(88.89,77.02) 88.72,77.28 88.42,77.58 87.33,78.67 arc(84.94,80.27) 82.12,80.83 57.07,80.83 arc(54.47,79.75) 53.39,77.14 53.39,76.94 arc(53.44,76.68) 53.58,76.46 53.85,76.07 53.85,75.69 U8.L36
TXP0_HOST_TOP: length 30.6
  TOP w0.16: U1.H9 v2(88.13,68.6)
  ART09 w0.109: v2(88.13,68.6) 87.86,68.33 87.86,68.22 arc(87.7,67.82) 87.29,67.65 86.48,67.65 arc(85.5,67.84) 84.68,68.4 80.81,72.27 arc(79.41,73.2) 77.75,73.53 65.83,73.53 arc(65.18,73.66) 64.64,74.03 arc(64.62,74.03) 64.6,74.05 arc(64.6,74.05) 64.59,74.06 arc(64.59,74.06) 64.58,74.07 arc(64.58,74.07) 64.58,74.07 arc(64.58,74.07) 64.58,74.07 64.43,74.22 arc(64.1,74.44) 63.7,74.52 63.45,74.52 arc(63.07,74.59) 62.75,74.81 62.52,75.04 62.49,75.09 62.27,75.41 61.57,75.41 U8.U36
TXP1_CABLE_BOT: length 49.5
  TOP w0.132: 119.88,67.01 119.86,67.03 119.53,67.03 arc(119.39,67.06) 119.27,67.14 119.1,67.3 arc(119,67.37) 118.87,67.4 U2.H5
  TOP w0.16: v2(121.88,67.01) 121.88,67.1 arc(121.74,67.43) 121.41,67.56 121.07,67.56 arc(120.99,67.56) 120.9,67.54 arc(120.79,67.48) 120.68,67.4 120.51,67.23 arc(120.27,67.07) 119.98,67.01 119.88,67.01
  ART11 w0.109: U9.L3 157.98,64.09 157.98,63.92 158.33,63.36 arc(158.45,63.11) 158.49,62.84 arc(158.45,62.66) 158.35,62.5 158.3,62.45 158.23,62.39 arc(157.97,62.21) 157.66,62.15 157.54,62.15 arc(157.28,62.1) 157.06,61.95 154.64,59.53 153.41,58.3 arc(151.06,56.73) 148.29,56.18 134.66,56.18 arc(132.12,56.69) 129.96,58.13 122.52,65.57 122.33,65.75 arc(122.14,66.05) 122.07,66.4 122.07,66.83 v2(121.88,67.01)
TXP1_CABLE_TOP: length 42
  TOP w0.16: U2.H13 v2(119.13,74.2)
  ART11 w0.109: U9.U3 150.01,64.12 150.01,63.91 150.42,63.19 arc(150.48,63.04) 150.5,62.89 150.5,62.64 arc(149.69,60.67) 147.72,59.86 138.48,59.86 arc(135.7,60.41) 133.34,61.98 126.58,68.75 125.09,70.23 124.56,70.76 arc(123.61,71.4) 122.47,71.63 120.8,71.63 arc(119.78,72.05) 119.35,73.08 119.35,73.98 v2(119.13,74.2)
TXP1_HOST_BOT: length 48.8
  TOP w0.132: U1.H5 88.39,72.2 arc(88.27,72.22) 88.16,72.3 87.99,72.46 arc(87.87,72.54) 87.73,72.57 87.4,72.57 87.39,72.57 87.37,72.59
  TOP w0.16: v2(85.38,72.59) 85.38,72.5 arc(85.52,72.17) 85.85,72.03 86.19,72.03 arc(86.28,72.04) 86.36,72.06 arc(86.48,72.11) 86.58,72.2 86.75,72.37 arc(87,72.53) 87.28,72.59 87.37,72.59
  ART11 w0.109: U8.L3 49.92,75.76 49.92,75.93 49.55,76.52 arc(49.45,76.71) 49.42,76.91 49.42,77.04 arc(49.47,77.25) 49.59,77.44 49.7,77.55 arc(49.9,77.7) 50.14,77.75 arc(50.36,77.8) 50.56,77.92 53.19,80.56 arc(56.59,82.82) 60.59,83.62 70.94,83.62 arc(75.01,82.81) 78.45,80.51 84.44,74.53 84.78,74.18 arc(85.09,73.72) 85.2,73.18 85.2,72.77 v2(85.38,72.59)
TXP1_HOST_TOP: length 40.8
  TOP w0.16: U1.H13 v2(88.13,65.4)
  ART11 w0.109: v2(88.13,65.4) 87.94,65.59 87.94,66.03 arc(87.38,67.39) 86.03,67.94 85.65,67.94 arc(83.98,68.28) 82.57,69.22 75.85,75.94 arc(71.53,78.83) 66.45,79.84 60.02,79.84 arc(58.17,79.07) 57.4,77.22 57.4,77.04 arc(57.43,76.83) 57.51,76.63 arc(57.55,76.56) 57.58,76.5 57.89,75.97 57.89,75.73 U8.U3
TXP2_CABLE_BOT: length 45.4
  TOP w0.16: U2.H3 v2(119.13,65.4)
  ART09 w0.109: U9.L33 154.26,66.78 153.75,66.78 153.63,66.89 153.36,67.33 arc(153.07,67.65) 152.65,67.77 152.16,67.77 arc(152.14,67.77) 152.12,67.76 arc(151.73,67.48) 151.58,67.03 151.58,63.86 arc(150.27,60.68) 147.09,59.36 136.33,59.36 arc(134.98,59.63) 133.83,60.4 130.46,63.77 arc(128,65.49) 125.09,66.27 arc(124.73,66.29) 124.36,66.3 119.9,66.3 arc(119.62,66.18) 119.5,65.9 119.5,65.77 v2(119.13,65.4)
TXP2_CABLE_TOP: length 31.5
  TOP w0.132: 119.64,72.57 119.53,72.57 arc(119.39,72.54) 119.27,72.46 119.1,72.3 arc(119,72.22) 118.87,72.2 U2.H11
  TOP w0.16: v2(122.88,72.59) 122.88,72.75 arc(122.84,72.96) 122.72,73.15 122.55,73.31 arc(122.27,73.5) 121.93,73.57 120.8,73.57 arc(120.25,73.34) 120.02,72.78 arc(119.96,72.64) 119.82,72.59 119.8,72.59 119.78,72.57 119.64,72.57
  ART09 w0.109: v2(122.88,72.59) 122.71,72.41 122.71,72.19 arc(122.87,71.79) 123.27,71.63 129.87,71.63 arc(132.09,71.19) 133.97,69.93 134.46,69.44 arc(136.25,68.24) 138.37,67.82 144.65,67.82 arc(144.93,67.76) 145.17,67.6 145.29,67.49 145.44,67.26 145.48,67.18 145.72,66.83 146.31,66.83 U9.U33
TXP2_HOST_BOT: length 42.4
  TOP w0.16: U1.H3 v2(88.13,74.2)
  ART09 w0.109: U8.L33 53.59,73.03 54.25,73.03 54.38,72.89 54.58,72.63 54.68,72.51 54.79,72.39 arc(55.08,72.2) 55.42,72.13 55.6,72.13 arc(56.1,72.34) 56.31,72.85 56.31,76 arc(56.42,76.54) 56.72,76.99 arc(58.07,77.89) 59.65,78.21 77.94,78.21 arc(79.44,77.91) 80.71,77.06 82.95,74.82 83.18,74.6 arc(84.64,73.62) 86.36,73.28 87.41,73.28 arc(87.78,73.44) 87.94,73.81 87.94,74.01 v2(88.13,74.2)
TXP2_HOST_TOP: length 31
  TOP w0.132: U1.H11 88.39,67.4 arc(88.27,67.37) 88.16,67.3 87.99,67.14 arc(87.87,67.06) 87.73,67.03 87.48,67.03 87.46,67.01
  TOP w0.16: 87.46,67.01 87.25,67.01 arc(87.02,67.06) 86.82,67.19 86.57,67.44 arc(86.48,67.51) 86.38,67.55 arc(86.32,67.56) 86.27,67.56 85.94,67.56 arc(85.54,67.4) v2(85.38,67.01)
  ART09 w0.109: v2(85.38,67.01) 85.17,66.8 85.17,66.55 arc(84.99,66.12) 84.56,65.94 82.62,65.94 arc(82.23,65.96) 81.85,66.04 arc(81.12,66.34) 80.49,66.82 77.69,69.62 arc(75.83,70.86) 73.63,71.3 66.13,71.3 arc(65.71,71.38) 65.35,71.62 arc(64.79,72) 64.12,72.13 63.38,72.13 arc(62.92,72.23) 62.58,72.56 62.29,73.08 62.23,73.17 62.22,73.19 62.04,73.24 U8.U33
TXP3_CABLE_BOT: length 51.1
  TOP w0.16: U2.H7 v2(119.13,68.6)
  ART11 w0.109: v2(119.13,68.6) 119.5,68.97 119.5,69.24 arc(119.7,69.73) 120.19,69.93 121.39,69.93 arc(123.08,69.59) 124.52,68.63 125.28,67.87 132.11,61.04 arc(135.18,58.99) 138.8,58.27 145.82,58.27 arc(150.31,59.17) 154.11,61.71 155.16,62.76 arc(155.48,63.24) 155.6,63.8 155.6,66.99 arc(155.87,67.56) 156.46,67.8 156.62,67.8 arc(156.97,67.72) 157.25,67.49 157.69,66.88 157.82,66.75 158.24,66.75 U9.L6
TXP3_CABLE_TOP: length 45.3
  TOP w0.16: U2.G15 v2(118.08,76.33)
  ART11 w0.109: v2(118.08,76.33) 118.41,76.66 118.41,76.89 arc(118.59,77.32) 119.02,77.5 119.53,77.5 arc(120.99,77.21) 122.23,76.38 134.4,64.22 arc(136.96,62.51) 139.98,61.9 145.88,61.9 arc(147.1,62.41) 147.6,63.63 147.6,67.11 arc(147.79,67.58) 148.26,67.77 148.72,67.77 arc(149.03,67.7) 149.27,67.49 149.65,66.89 149.76,66.78 150.26,66.78 U9.U6
TXP3_HOST_BOT: length 50.7
  TOP w0.16: U1.H7 v2(88.13,71)
  ART11 w0.109: v2(88.13,71) 87.86,70.73 87.86,70.59 arc(87.64,70.04) 87.1,69.82 85.7,69.82 arc(84.66,70.03) 83.78,70.61 82.91,71.48 75.5,78.89 arc(72.61,80.83) 69.19,81.51 61.21,81.51 arc(56.94,80.66) 53.32,78.24 53.01,77.93 arc(52.49,77.15) 52.31,76.24 52.31,72.87 arc(52.09,72.35) 51.57,72.13 51.26,72.13 arc(51,72.18) 50.78,72.34 arc(50.77,72.35) 50.76,72.35 50.7,72.44 arc(50.69,72.46) 50.68,72.48 50.33,72.98 50.24,73.08 49.64,73.08 U8.L6
TXP3_HOST_TOP: length 44.1
  TOP w0.16: U1.G15 v2(89.19,63.27)
  ART11 w0.109: v2(89.19,63.27) 88.96,63.04 88.96,62.79 arc(88.76,62.32) 88.29,62.12 87.3,62.12 arc(86.5,62.28) 85.82,62.74 78.37,70.18 75.71,72.84 arc(70.39,76.4) 64.11,77.65 62.03,77.65 arc(60.82,77.15) 60.33,75.95 60.33,72.75 arc(60.12,72.26) 59.63,72.05 59.39,72.05 arc(59.09,72.11) 58.84,72.27 arc(58.83,72.28) 58.83,72.29 58.31,72.97 58.18,73.1 57.66,73.1 U8.U6
VUSB: length 68
  ART04 w0.254: v1(92.71,29.21) 91.06,29.21 89.39,30.88 89.39,34.31 88.39,35.31 80.77,35.31 71.75,26.29 68.44,26.29 66.79,24.64 37.97,24.64 v1(37.47,24.13) v1(37.47,22.86)
  BOTTOM w0.254: U3.66 93.56,30.44 92.71,29.59 v1(92.71,29.21)
WP: length 5.6
  TOP w0.183: J18.7 13.97,31.11 J19.2
N16780616: length 19.1
  TOP w0.305: v1(97.79,34.29) 97.8,34.3 C32.2 99.81,34.3 100.46,33.66 101.09,33.66 101.85,34.42 103.2,34.42 104.22,35.43 Y1.1
  BOTTOM w0.254: 96.12,29.06 96,28.94 U3.69
  BOTTOM w0.305: 96.12,29.06 96.52,29.46 96.52,33.02 v1(97.79,34.29)
N16780624: length 17.4
  TOP w0.305: v1(97.79,32.38) 97.8,32.38 C31.2 99.81,32.38 100.46,33.02 101.22,33.02 101.98,33.78 103.63,33.78 104.22,33.2 Y1.2
  BOTTOM w0.254: U3.70 96.39,28.44 96.54,28.6
  BOTTOM w0.305: v1(97.79,32.38) 97.79,32.37 97.16,31.73 97.16,29.21 96.54,28.6
N16780665: length 10.5
  BOTTOM w0.203: U3.72 96.76,27.44 100.48,23.72 J2.1
N16780674: length 7.3
  TOP w0.183: Q1.1 82.05,16.65 v1(82.55,17.14)
  BOTTOM w0.203: v1(82.55,17.14) 82.55,17.78 85.28,20.51 U3.15
N16780676: length 20.9
  BOTTOM w0.203: J2.8 104.52,17.37 104.52,25.02 104.27,25.27 99.95,25.27 97.28,27.94 U3.71
N16780680: length 11.4
  BOTTOM w0.203: J2.3 102.13,21.18 96.37,26.94 U3.73
N16780690: length 12.7
  BOTTOM w0.203: J2.5 102.9,18.64 101.6,19.94 101.6,20.83 95.98,26.44 U3.74
N16780698: length 14.3
  BOTTOM w0.203: J2.7 100.33,19.02 100.33,21.08 95.47,25.94 U3.75
N16780708: length 20.2
  TOP w0.183: v1(95.89,24.13) 96.52,23.5 C30.1 98.4,22.85 R25.1 99.05,22.87 100.33,21.59 100.33,13.94 J2.11
  BOTTOM w0.183: U3.76 95.21,25.44 95.89,24.77 v1(95.89,24.13)
N16780744: length 2.4
  TOP w0.183: R26.1 87.51,13.51 D1.2
N16780746: length 3.2
  TOP w0.183: Q1.2 84.05,13.3 R26.2
N16780748: length 8.5
  TOP w0.183: v1(78.74,17.14) 78.11,16.51 C34.1
  BOTTOM w0.203: U3.20 82.78,20.55 81.92,19.68 81.28,19.68 v1(78.74,17.14)
N16782058: length 9.3
  TOP w0.16: J6.2 30.95,10.08 31.75,10.89 31.75,12.25 31.34,12.66 31.34,13.46 31.11,13.69 v1(31.11,13.97) 31.11,14.41 30.48,15.04 R28.1
  BOTTOM w0.16: U4.1 30.87,13.72 v1(31.11,13.97)
N16782064: length 9.6
  TOP w0.16: R29.1 31.75,12.83 32.16,12.42 32.16,11.66 v1(32.38,11.43) 32.16,11.2 32.16,10.72 31.36,9.92 31.36,9.61 31.75,9.22 J6.3
  BOTTOM w0.16: U4.4 31.87,11.95 v1(32.38,11.43)
N16782724: length 2.5
  TOP w0.305: C40.2 57.15,19.67 56.83,19.35 U5.3
N16869157: length 2.3
  TOP w0.183: U6.1 105.54,46.35 104.89,45.71 R33.1
N16869235: length 2.2
  TOP w0.183: R34.1 U6.3
N16899401: length 3.8
  TOP w0.183: R11.1 J16.1
N16899406: length 3.8
  TOP w0.183: R19.2 J16.3
N16899979: length 3.8
  TOP w0.183: R47.2 J17.3
N16900523: length 3.2
  TOP w0.183: R49.2 J18.1
N16900525: length 3.2
  TOP w0.183: R48.2 J18.2
N16900527: length 3.2
  TOP w0.183: R27.2 J18.3
N16901581: length 3.8
  TOP w0.183: R50.1 J19.1
N16901585: length 3.8
  TOP w0.183: R51.2 J19.3
N16901924: length 3.2
  TOP w0.183: R52.1 J20.1
N16901939: length 3.2
  TOP w0.183: R53.2 J20.3
N16902597: length 3.2
  TOP w0.183: R54.1 J21.1
N16902612: length 3.2
  TOP w0.183: R55.2 J21.3
N16903155: length 3.2
  TOP w0.183: R22.1 J22.2
N16903160: length 3.2
  TOP w0.183: R15.1 J22.1
N168714110: length 2.2
  TOP w0.508: D3.2 R37.1
N168716471: length 2.2
  TOP w0.508: D4.2 R38.2

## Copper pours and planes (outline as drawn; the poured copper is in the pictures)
GND on TOP (solid shape): 148.97,51.44 148.97,49.66 148.59,49.28 144.65,49.28 144.27,49.66 144.27,51.31 144.65,51.69 148.72,51.69
GND on TOP (solid shape): outline of 12599 points within 0.51,0.51 207.37,98.02
GND on BOTTOM (solid shape): outline of 19173 points within 0.51,0.51 207.37,98.02
GND on ART02 (solid shape): outline of 29274 points within 0.51,0.51 207.37,98.02
GND on GND03 (solid shape): outline of 29456 points within 0.51,0.51 207.36,98.02
GND on GND05 (solid shape): outline of 28384 points within 0.51,0.51 207.36,98.02
GND on GND08 (solid shape): outline of 28384 points within 0.51,0.51 207.36,98.02
GND on GND10 (solid shape): outline of 28384 points within 0.51,0.51 207.36,98.02
VBUS on TOP (solid shape): 48.13,17.53 50.67,17.53 51.82,16.38 51.82,13.84 50.04,12.06 37.21,12.06 36.45,12.83 36.45,18.16 36.96,18.67 46.99,18.67
VBUS on TOP (solid shape): 30.37,10.9 30.37,6.5 30.23,6.35 29.08,6.35 28.69,6.74 28.69,9.16 28.6,9.25 28.6,9.28 28.57,9.28 28.3,9.55 28.3,10.9 28.57,11.18 30.1,11.18
VBUS on POWER07 (solid shape): outline of 4560 points within 1.02,1.02 99.69,44.45
VDD_2P5V on TOP (solid shape): 187.71,23.37 189.61,23.37 189.69,23.44 189.74,23.44 190.17,23.88 193.68,23.88 194.56,22.99 194.56,7.37 191.52,4.32 176.02,4.32 173.23,7.11 173.23,14.35 175.26,16.38 179.2,16.38 184.53,21.72 184.53,23.24 185.17,23.88 187.2,23.88
VDD_2P5V on BOTTOM (solid shape): 91.62,72.67 91.62,71.6 91.95,71.27 91.95,70.76 92.46,70.26 92.46,68.48 92.2,68.22 92.2,67.46 92.18,67.44 92.15,67.43 92,67.41 91.87,67.35 91.86,67.34 91.6,67.34 91.59,67.35 91.33,67.43 91.07,67.35 91.06,67.34 90.8,67.34 90.79,67.35 90.65,67.42 90.48,67.43 90.47,67.43 90.45,67.44 90.42,67.46 90.42,68.96 90.41,68.97 90.41,69.15 89.69,69.88 89.69,70.51 90.2,71.02 90.2,72.77 90.37,72.95 91.34,72.95
VDD_2P5V on BOTTOM (solid shape): 115.67,72.25 115.93,72.17 116.19,72.25 116.2,72.26 116.46,72.26 116.47,72.25 116.62,72.18 116.78,72.17 116.79,72.17 116.81,72.16 116.84,72.14 116.84,70.64 116.85,70.62 116.85,70.45 117.58,69.72 117.58,69.09 117.07,68.58 117.07,66.83 116.89,66.65 115.93,66.65 115.65,66.93 115.65,68 115.32,68.33 115.32,68.83 114.81,69.34 114.81,71.12 115.06,71.37 115.06,72.14 115.09,72.16 115.12,72.17 115.26,72.19 115.39,72.25 115.4,72.26 115.66,72.26
VDD_2P5V on POWER06 (solid shape): outline of 42290 points within 1.02,1.02 206.86,97.51
VDD_2P5V_REG on TOP (solid shape): 161.16,28.07 161.16,23.11 161.73,22.54 161.73,21.46 161.99,21.21 162.94,21.21 163.3,21.57 163.33,21.57 163.33,21.6 164.34,22.61 164.34,23.5 165.23,24.38 168.78,24.38 168.97,24.57 182.94,24.57 183.26,24.26 183.26,21.97 178.56,17.27 162.18,17.27 159.89,19.56 159.89,28.19 160.02,28.32 160.91,28.32
VDD_3P3V on TOP (solid shape): 122.56,38.48 122.56,33.4 122.05,32.89 110.24,32.89 109.73,33.4 109.73,38.48 110.11,38.86 122.17,38.86
VDD_3P3V on TOP (solid shape): 157.86,28.07 157.86,19.68 152.02,13.84 152.02,3.94 151.38,3.3 133.6,3.3 131.95,4.95 131.95,20.95 133.22,22.23 136.74,22.23 136.74,22.22 137.62,22.22 137.67,22.17 139.17,22.17 139.17,22.17 140.73,22.17 140.73,22.19 140.77,22.23 142.88,22.23 145.16,24.51 145.16,26.67 145.29,26.8 146.69,26.8 146.81,26.67 146.81,24.89 148.15,23.56 155.64,23.56 156.34,24.26 156.34,27.94 156.72,28.32 157.61,28.32
VDD_3P3V on POWER07 (solid shape): outline of 9755 points within 100.33,1.02 206.86,38.73
VDD_3P3V_USB on TOP (solid shape): 88.52,20.45 88.52,15.49 88.14,15.11 86.87,15.11 86.61,15.37 86.61,19.3 86.11,19.81 83.57,19.81 83.44,19.94 83.44,20.7 83.57,20.83 88.14,20.83
VDD_3P3V_USB on TOP (solid shape): 63.87,19.22 63.87,18.05 63.88,18.03 63.88,16.13 63.25,15.49 60.96,15.49 59.18,17.27 55.24,17.27 55.09,17.42 55.09,18.08 55.22,18.21 56.44,18.21 57.02,18.8 58.42,18.8 59.44,19.81 63.27,19.81
VDD_3P3V_USB on POWER07 (solid shape): outline of 3006 points within 57.15,1.02 99.82,36.83
QSFP_VCC_3P3V on TOP (solid shape): 159,55.63 159,52.7 158.62,52.32 144.53,52.32 143.38,51.18 140.97,51.18 140.72,51.44 140.72,55.63 140.97,55.88 158.75,55.88
QSFP_VCC_3P3V on TOP (solid shape): 59.44,54.74 59.44,50.8 58.86,50.23 56.45,50.23 53.59,53.09 48.9,53.09 47.5,51.69 31.5,51.69 30.99,52.2 30.99,54.86 31.75,55.63 58.55,55.63
QSFP_VCC_3P3V on TOP (solid shape): 122.56,44.83 122.56,40.01 122.17,39.62 110.11,39.62 109.73,40.01 109.73,43.53 109.73,43.54 109.8,43.75 109.78,43.98 109.78,43.99 109.78,45.01 109.98,45.21 122.17,45.21
QSFP_VCC_3P3V on POWER07 (solid shape): outline of 19676 points within 1.02,40.01 206.86,97.51
VUSB on TOP (solid shape): 37.85,24.13 37.85,22.73 35.94,20.83 32.45,20.83 32.35,20.9 32.38,21.01 31.75,22.8 31.12,21.01 31.15,20.9 31.05,20.83 29.34,20.83 28.96,21.21 28.96,24.13 29.34,24.51 37.47,24.51
N16782035 on TOP (solid shape): 27.94,13.08 27.94,8.89 28.32,8.51 28.32,5.59 28.8,5.1 28.81,5.09 29.02,4.69 29.41,4.48 29.43,4.48 29.59,4.32 34.04,4.32 34.25,4.53 34.26,4.53 34.48,4.69 34.64,4.92 34.64,4.93 34.8,5.08 34.8,9.14 35.31,9.65 37.08,9.65 37.97,8.76 37.97,1.14 37.47,0.64 26.16,0.64 24.26,2.54 24.26,12.7 24.77,13.21 27.81,13.21
N16782665 on TOP (solid shape): 52.96,20.7 52.96,20.23 52.93,20.2 52.92,20.2 52.92,19.88 52.9,19.84 52.87,19.83 51.77,19.83 51.77,18.22 52.87,18.22 52.9,18.2 52.92,18.17 52.92,17.84 52.93,17.84 52.96,17.81 52.96,17.53 52.7,17.27 51.44,17.27 50.95,17.76 50.95,17.81 50.9,17.81 50.67,18.03 49.53,18.03 49.15,18.41 49.15,20.45 49.53,20.83 52.83,20.83

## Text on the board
